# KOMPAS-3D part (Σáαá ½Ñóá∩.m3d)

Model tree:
1. Эскиз:1
2. Операция выдавливания:1
     Расстояние 1 = 1; Расстояние 2 = 6
3. Скругление:1
     Радиус = 5
4. Эскиз:2
5. Операция выдавливания:2
     Расстояние 1 = 1; Расстояние 2 = 2
6. Эскиз:3
7. Вырезать элемент выдавливания:1
     Расстояние 1 = 0.1
8. Плоскость, касательная в точке:1
9. Эскиз:4
10. Операция выдавливания:3
     Расстояние 1 = 1; Расстояние 2 = 2
11. Эскиз:5
12. Вырезать элемент выдавливания:2
     Расстояние 1 = 8
13. Эскиз:6
14. Операция выдавливания:4
     Расстояние 1 = 0.7; Расстояние 2 = 2
15. Эскиз:7
16. Операция выдавливания:5
     Расстояние 1 = 0.7; Расстояние 2 = 1
17. Эскиз:9
18. Вырезать элемент выдавливания:3
     Расстояние 1 = 3.08889
19. Скругление:3
     Радиус = 0.2
20. Эскиз:10
21. Операция выдавливания:6
     Расстояние 1 = 0.8; Расстояние 2 = 1
22. Эскиз:11
23. Операция выдавливания:7
     Расстояние 1 = 1.8; Расстояние 2 = 1
24. Эскиз:12
25. Операция выдавливания:8
     Расстояние 1 = 1; Расстояние 2 = 1
26. Эскиз:13
27. Операция выдавливания:9
     Расстояние 1 = 0.1; Расстояние 2 = 1.3
28. Эскиз:14
29. Операция выдавливания:10
     Расстояние 1 = 0.2; Расстояние 2 = 1.3
30. Эскиз:15
31. Операция выдавливания:11
     Расстояние 1 = 0.1; Расстояние 2 = 1.3
32. Скругление:4
     Радиус = 0.1
33. Массив по концентрической сетке:1  (with: Операция выдавливания:11, Скругление:4)  (labels: Экземпляр ( 1, 1 ); Экземпляр ( 1, 2 ); Экземпляр ( 1, 3 ); Экземпляр ( 1, 4 ))
     N 2 = 5; Шаг 2 = 360; Номер 2 = 1
34. Массив по концентрической сетке:2  (with: Операция выдавливания:3, Вырезать элемент выдавливания:2, Операция выдавливания:4, Операция выдавливания:5, Вырезать элемент выдавливания:3, Скругление:3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)  (labels: Экземпляр ( 1, 1 ); Экземпляр ( 1, 2 ); Экземпляр ( 1, 3 ); Экземпляр ( 1, 4 ))
     N 2 = 4; Шаг 2 = 360; Номер 2 = 1
35. Эскиз:16
36. Операция выдавливания:12
     Расстояние 1 = 0.1; Расстояние 2 = 5
37. Скругление:6
     Радиус = 0.3
38. Эскиз:17
39. Вырезать элемент выдавливания:4
     Расстояние 1 = 2
40. Эскиз:21
41. Операция выдавливания:16
     Расстояние 1 = 5.5; Расстояние 2 = 8
42. Эскиз:22
43. Операция выдавливания:17
     Расстояние 1 = 5; Расстояние 2 = 8
44. Скругление:8
     Радиус = 0.2
45. Скругление:9
     Радиус = 0.2
46. Эскиз:23
47. Операция выдавливания:18
     Расстояние 1 = 0.1; Расстояние 2 = 8
48. Скругление:10
     Радиус = 0.1
49. Эскиз:24
50. Операция выдавливания:19
     Расстояние 1 = 0.1; Расстояние 2 = 1.1
51. Эскиз:25
52. Вырезать элемент выдавливания:5
     Расстояние 2 = 4; Расстояние 1 = 4

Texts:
  stalker61
  Сплав АЛ8  ГОСТ 1583-93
